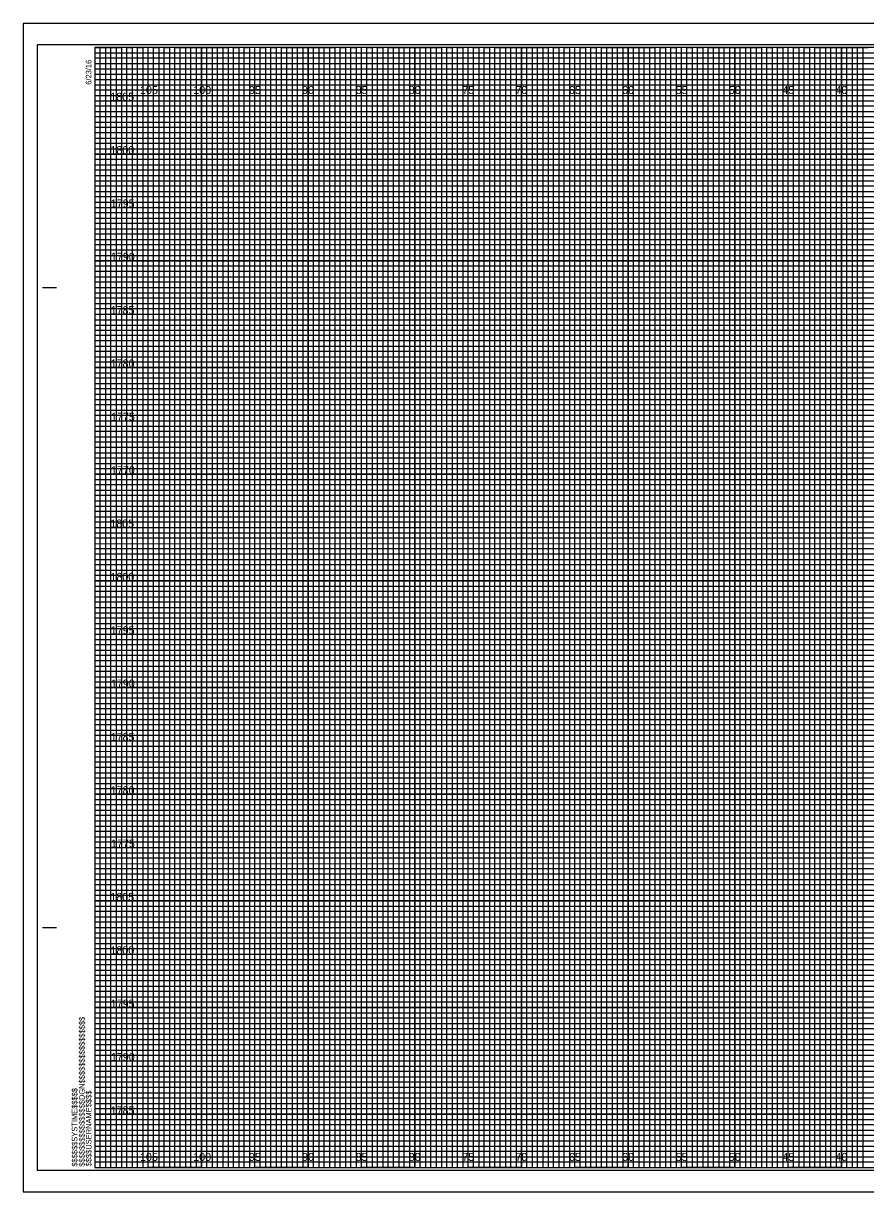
# Model space of a CAD drawing. Extents: x -7 to 392, y -2 to 440.
# Drawn here: x 223.6 to 302.5, y 1 to 110.5 of the extents above; entities that cross this region are included whole.
import ezdxf

# ---------------------------------------------------------------- set-up
doc = ezdxf.new("R2010")
doc.units = 0
for name, color, linetype in [('Prop Grid Mask', 7, 'Continuous'), ('Prop XS Elevation Labels', 7, 'Continuous'), ('Sheet Cross Section CELL', 7, 'Continuous'), ('Sheet Cross Section Grid Major CELL', 7, 'Continuous'), ('Sheet Cross Section Grid Middle CELL', 7, 'Continuous'), ('Sheet Cross Section Grid Minor 1 CELL', 7, 'Continuous'), ('Sheet Cross Section Grid Minor 2 CELL', 7, 'Continuous'), ('Sheet Cutting Line CELL', 7, 'Continuous'), ('Sheet DOT Grid CELL', 7, 'Continuous'), ('Sheet Plot Border Inside CELL', 7, 'Continuous'), ('Sheet Plot Border Outside CELL', 7, 'Continuous')]:
    doc.layers.add(name, color=color, linetype=linetype)

msp = doc.modelspace()

# ---------------------------------------------------------------- linework, layer by layer
at = {"layer": 'Sheet Cross Section CELL'}
for p, q in [((225.36, 85.71), (226.61, 85.71)), ((225.41, 85.71), (226.66, 85.71)), ((225.36, 25.71), (226.61, 25.71)), ((225.41, 25.71), (226.66, 25.71)), ((230.26, 3.21), (230.26, 3.21)), ((230.26, 3.21), (230.26, 3.21)), ((230.26, 3.21), (230.26, 3.21)), ((230.26, 3.21), (230.26, 3.21)), ((230.26, 3.21), (230.26, 3.21)), ((230.26, 3.21), (230.26, 3.21)), ((230.26, 3.21), (230.26, 3.21))]:
    msp.add_line(p, q, dxfattribs=at)
msp.add_lwpolyline([(390.26, 108.21), (230.26, 108.21), (230.26, 3.21), (390.26, 3.21)], close=True, dxfattribs=at)
at = {"layer": 'Sheet Cross Section Grid Major CELL'}
for p, q in [((235.26, 108.21), (230.26, 108.21)), ((235.26, 3.21), (235.26, 108.21)), ((245.26, 108.21), (240.26, 108.21)), ((240.26, 108.21), (240.26, 3.21)), ((245.26, 3.21), (245.26, 108.21)), ((255.26, 108.21), (250.26, 108.21)), ((250.26, 108.21), (250.26, 3.21)), ((255.26, 3.21), (255.26, 108.21)), ((265.26, 108.21), (260.26, 108.21)), ((260.26, 108.21), (260.26, 3.21)), ((265.26, 3.21), (265.26, 108.21)), ((275.26, 108.21), (270.26, 108.21)), ((270.26, 108.21), (270.26, 3.21)), ((275.26, 3.21), (275.26, 108.21)), ((285.26, 108.21), (280.26, 108.21)), ((280.26, 108.21), (280.26, 3.21)), ((285.26, 3.21), (285.26, 108.21)), ((295.26, 108.21), (290.26, 108.21)), ((290.26, 108.21), (290.26, 3.21)), ((295.26, 3.21), (295.26, 108.21)), ((305.26, 108.21), (300.26, 108.21)), ((300.26, 108.21), (300.26, 3.21)), ((240.26, 3.21), (235.26, 3.21)), ((250.26, 3.21), (245.26, 3.21)), ((260.26, 3.21), (255.26, 3.21)), ((270.26, 3.21), (265.26, 3.21)), ((280.26, 3.21), (275.26, 3.21)), ((290.26, 3.21), (285.26, 3.21)), ((300.26, 3.21), (295.26, 3.21))]:
    msp.add_line(p, q, dxfattribs=at)
for points in [[(230.26, 103.21), (390.26, 103.21), (390.26, 98.21), (230.26, 98.21)], [(230.26, 93.21), (390.26, 93.21), (390.26, 88.21), (230.26, 88.21)], [(230.26, 83.21), (390.26, 83.21), (390.26, 78.21), (230.26, 78.21)], [(230.26, 73.21), (390.26, 73.21), (390.26, 68.21), (230.26, 68.21)], [(230.26, 63.21), (390.26, 63.21), (390.26, 58.21), (230.26, 58.21)], [(230.26, 53.21), (390.26, 53.21), (390.26, 48.21), (230.26, 48.21)], [(230.26, 43.21), (390.26, 43.21), (390.26, 38.21), (230.26, 38.21)], [(230.26, 33.21), (390.26, 33.21), (390.26, 28.21), (230.26, 28.21)], [(230.26, 23.21), (390.26, 23.21), (390.26, 18.21), (230.26, 18.21)], [(230.26, 13.21), (390.26, 13.21), (390.26, 8.21), (230.26, 8.21)]]:
    msp.add_lwpolyline(points, dxfattribs=at)
at = {"layer": 'Sheet Cross Section Grid Middle CELL'}
for points in [[(230.26, 108.21), (232.76, 108.21), (232.76, 3.21), (237.76, 3.21), (237.76, 108.21), (242.76, 108.21), (242.76, 3.21), (247.76, 3.21), (247.76, 108.21), (252.76, 108.21), (252.76, 3.21), (257.76, 3.21), (257.76, 108.21), (262.76, 108.21), (262.76, 3.21), (267.76, 3.21), (267.76, 108.21), (272.76, 108.21), (272.76, 3.21), (277.76, 3.21), (277.76, 108.21), (282.76, 108.21), (282.76, 3.21), (287.76, 3.21), (287.76, 108.21), (292.76, 108.21), (292.76, 3.21), (297.76, 3.21), (297.76, 108.21), (302.76, 108.21)], [(230.26, 105.71), (367.76, 105.71)], [(230.26, 95.71), (390.26, 95.71), (390.26, 100.71), (230.26, 100.71)], [(230.26, 85.71), (390.26, 85.71), (390.26, 90.71), (230.26, 90.71)], [(230.26, 75.71), (390.26, 75.71), (390.26, 80.71), (230.26, 80.71)], [(230.26, 65.71), (390.26, 65.71), (390.26, 70.71), (230.26, 70.71)], [(230.26, 55.71), (390.26, 55.71), (390.26, 60.71), (230.26, 60.71)], [(230.26, 45.71), (390.26, 45.71), (390.26, 50.71), (230.26, 50.71)], [(230.26, 35.71), (390.26, 35.71), (390.26, 40.71), (230.26, 40.71)], [(230.26, 25.71), (390.26, 25.71), (390.26, 30.71), (230.26, 30.71)], [(230.26, 15.71), (390.26, 15.71), (390.26, 20.71), (230.26, 20.71)], [(230.26, 5.71), (390.26, 5.71), (390.26, 10.71), (230.26, 10.71)]]:
    msp.add_lwpolyline(points, dxfattribs=at)
at = {"layer": 'Sheet Cross Section Grid Minor 1 CELL'}
for p, q in [((230.26, 107.71), (360.26, 107.71)), ((360.26, 107.2), (230.26, 107.2)), ((230.26, 107.2), (230.26, 106.71)), ((230.26, 106.71), (360.26, 106.71)), ((360.26, 106.16), (230.26, 106.16)), ((230.26, 106.16), (230.26, 105.21)), ((230.26, 105.21), (390.26, 105.21))]:
    msp.add_line(p, q, dxfattribs=at)
for points in [[(230.26, 104.71), (365.26, 104.71), (390.26, 104.71), (390.26, 104.21), (230.26, 104.21)], [(230.26, 103.71), (390.26, 103.71), (390.26, 102.71), (230.26, 102.71)], [(230.26, 102.21), (390.26, 102.21), (390.26, 101.71), (230.26, 101.7)], [(230.26, 101.21), (390.26, 101.21), (390.26, 100.21), (230.26, 100.21)], [(230.26, 99.71), (390.26, 99.71), (390.26, 99.21), (230.26, 99.21)], [(230.26, 98.71), (390.26, 98.71), (390.26, 97.71), (230.26, 97.71)], [(230.26, 97.21), (390.26, 97.21), (390.26, 96.71), (230.26, 96.71)], [(230.26, 96.21), (390.26, 96.21), (390.26, 95.21), (230.26, 95.21)], [(230.26, 94.71), (390.26, 94.71), (390.26, 94.21), (230.26, 94.21)], [(230.26, 93.71), (390.26, 93.71), (390.26, 92.71), (230.26, 92.71)], [(230.26, 92.21), (390.26, 92.21), (390.26, 91.71), (230.26, 91.71)], [(230.26, 91.21), (390.26, 91.21), (390.26, 90.19), (390.26, 89.71), (390.26, 89.21), (230.26, 89.21)], [(230.26, 90.21), (390.26, 90.21), (390.26, 89.71), (230.26, 89.71)], [(230.26, 88.71), (390.26, 88.71), (390.26, 87.71), (230.26, 87.73)], [(230.26, 87.73), (390.26, 87.71), (390.26, 87.21), (230.26, 87.21)], [(230.26, 86.71), (390.26, 86.71), (390.26, 86.21), (230.26, 86.21)], [(230.26, 85.21), (390.26, 85.21), (390.26, 84.71), (230.26, 84.71)], [(230.26, 84.21), (390.26, 84.21), (390.26, 83.71), (230.26, 83.71)], [(230.23, 82.66), (390.26, 82.66), (390.26, 82.15), (230.23, 82.15)], [(230.26, 81.71), (390.26, 81.71), (390.26, 81.21), (230.26, 81.21)], [(230.26, 80.21), (390.26, 80.21), (390.26, 79.71), (230.26, 79.71)], [(230.26, 79.21), (390.26, 79.21), (390.26, 78.71), (230.26, 78.71)], [(230.26, 77.71), (390.26, 77.71), (390.26, 77.21), (230.26, 77.21)], [(230.26, 76.71), (390.26, 76.71), (390.26, 76.21), (230.26, 76.21)], [(230.26, 75.21), (390.26, 75.21), (390.26, 74.71), (230.26, 74.71)], [(230.26, 74.21), (390.26, 74.21), (390.26, 73.71), (230.26, 73.71)], [(230.26, 72.71), (390.26, 72.71), (390.26, 72.2), (230.26, 72.21)], [(230.26, 71.71), (390.26, 71.71), (390.26, 71.21), (230.26, 71.21)], [(230.26, 70.21), (390.26, 70.21), (390.26, 69.71), (230.26, 69.71)], [(230.26, 69.21), (390.26, 69.21), (390.26, 68.71), (230.26, 68.71)], [(230.26, 67.71), (390.26, 67.71), (390.26, 67.21), (230.26, 67.21)], [(230.26, 66.71), (390.26, 66.71), (390.26, 66.21), (230.26, 66.21)], [(230.26, 65.21), (390.26, 65.21), (390.26, 64.71), (230.26, 64.71)], [(230.26, 64.21), (390.26, 64.21), (390.26, 63.71), (230.26, 63.71)], [(230.26, 62.71), (390.26, 62.71), (390.26, 62.21), (230.26, 62.21)], [(230.26, 61.71), (390.3, 61.67), (390.26, 61.21), (230.26, 61.21)], [(230.26, 60.21), (390.26, 60.21), (390.26, 59.71), (230.26, 59.71)], [(230.26, 59.21), (390.26, 59.21), (390.26, 58.71), (230.26, 58.71)], [(230.26, 57.71), (390.26, 57.71), (390.26, 57.21), (230.26, 57.21)], [(230.26, 56.71), (390.26, 56.71), (390.26, 56.21), (230.26, 56.21)], [(230.26, 55.21), (390.26, 55.21), (390.26, 54.71), (230.26, 54.71)], [(230.26, 54.21), (390.26, 54.21), (390.26, 53.71), (230.26, 53.71)], [(230.26, 52.71), (390.26, 52.71), (390.26, 52.21), (230.26, 52.21)], [(230.26, 51.71), (390.26, 51.71), (390.26, 51.21), (230.26, 51.21)], [(230.26, 50.21), (390.26, 50.21), (390.26, 49.71), (230.26, 49.71)], [(230.26, 49.21), (390.26, 49.21), (390.26, 48.71), (230.26, 48.71)], [(230.26, 47.71), (390.26, 47.71), (390.26, 47.21), (230.26, 47.21)], [(230.26, 46.71), (390.26, 46.71), (390.26, 46.21), (230.26, 46.21)], [(230.26, 45.21), (390.26, 45.21), (390.26, 44.71), (230.26, 44.71)], [(230.26, 44.21), (390.26, 44.21), (390.26, 43.71), (230.26, 43.71)], [(230.26, 42.71), (390.26, 42.71), (390.26, 42.2), (230.26, 42.21)], [(230.26, 41.71), (390.26, 41.71), (390.26, 41.21), (230.26, 41.21)], [(230.26, 40.21), (390.26, 40.21), (390.26, 39.71), (230.26, 39.71)], [(230.26, 39.21), (390.26, 39.21), (390.26, 38.71), (230.26, 38.71)], [(230.26, 37.71), (390.26, 37.71), (390.26, 37.21), (230.26, 37.21)], [(230.26, 36.71), (390.26, 36.71), (390.26, 36.21), (230.26, 36.21)], [(230.26, 35.21), (390.26, 35.21), (390.26, 34.71), (230.26, 34.71)], [(230.26, 34.21), (390.26, 34.21), (390.26, 33.71), (230.26, 33.71)], [(230.26, 32.71), (390.26, 32.71), (390.26, 32.21), (230.26, 32.21)], [(230.26, 31.71), (390.3, 31.67), (390.26, 31.21), (230.26, 31.21)], [(230.26, 30.21), (390.26, 30.21), (390.26, 29.71), (230.26, 29.71)], [(230.26, 29.21), (390.26, 29.21), (390.26, 28.71), (230.26, 28.71)], [(230.26, 27.71), (390.26, 27.71), (390.26, 27.21), (230.26, 27.21)], [(230.26, 26.71), (390.26, 26.71), (390.26, 26.21), (230.26, 26.21)], [(230.26, 25.21), (390.26, 25.21), (390.26, 24.71), (230.26, 24.71)], [(230.26, 24.21), (390.26, 24.21), (390.26, 23.71), (230.26, 23.71)], [(230.26, 22.71), (390.26, 22.71), (390.26, 22.21), (230.26, 22.21)], [(230.26, 21.71), (390.26, 21.71), (390.26, 21.21), (230.26, 21.21)], [(230.26, 20.21), (390.26, 20.21), (390.26, 19.71), (230.26, 19.71)], [(230.26, 19.21), (390.26, 19.21), (390.26, 18.71), (230.26, 18.71)], [(230.26, 17.71), (390.26, 17.71), (390.26, 17.21), (230.26, 17.21)], [(230.26, 16.71), (390.26, 16.71), (390.26, 16.21), (230.26, 16.21)], [(230.26, 15.21), (390.26, 15.21), (390.26, 14.71), (230.26, 14.71)], [(230.26, 14.21), (390.26, 14.21), (390.26, 13.71), (230.26, 13.71)], [(230.26, 12.71), (390.26, 12.71), (390.26, 12.21), (230.26, 12.21)], [(230.26, 11.71), (390.26, 11.71), (390.26, 11.21), (230.26, 11.21)], [(230.26, 10.21), (390.26, 10.21), (390.26, 9.71), (230.26, 9.71)], [(230.26, 9.21), (390.26, 9.21), (390.26, 8.71), (230.26, 8.71)], [(230.26, 7.71), (390.26, 7.71), (390.26, 7.21), (230.26, 7.21)], [(230.26, 6.71), (390.26, 6.71), (390.26, 6.21), (230.26, 6.21)], [(230.26, 5.21), (390.26, 5.21), (390.26, 4.71), (230.26, 4.71)], [(230.26, 4.21), (390.26, 4.21), (390.26, 3.71), (230.26, 3.71)]]:
    msp.add_lwpolyline(points, dxfattribs=at)
at = {"layer": 'Sheet Cross Section Grid Minor 2 CELL'}
for points in [[(230.26, 3.21), (230.76, 3.21), (230.76, 108.21), (231.26, 108.21), (231.26, 3.21)], [(231.26, 3.21), (231.76, 3.21), (231.76, 108.21), (232.26, 108.21), (232.26, 3.21)], [(232.76, 3.21), (233.26, 3.21), (233.26, 108.21), (233.76, 108.21), (233.76, 3.21)], [(233.76, 3.21), (234.26, 3.21), (234.26, 108.21), (234.76, 108.21), (234.76, 3.21)], [(235.26, 3.21), (235.76, 3.21), (235.76, 108.21), (236.26, 108.21), (236.26, 3.21)], [(236.26, 3.21), (236.76, 3.21), (236.76, 108.21), (237.26, 108.21), (237.26, 3.21)], [(237.76, 3.21), (238.26, 3.21), (238.26, 108.21), (238.76, 108.21), (238.76, 3.21)], [(238.76, 3.21), (239.26, 3.21), (239.26, 108.21), (239.76, 108.21), (239.76, 3.21)], [(240.26, 3.21), (240.76, 3.21), (240.76, 108.21), (241.26, 108.21), (241.26, 3.21)], [(241.26, 3.21), (241.76, 3.21), (241.76, 108.21), (242.26, 108.21), (242.26, 3.21)], [(242.76, 3.21), (243.26, 3.21), (243.26, 108.21), (243.76, 108.21), (243.76, 3.21)], [(243.76, 3.21), (244.26, 3.21), (244.26, 108.21), (244.76, 108.21), (244.76, 3.21)], [(245.26, 3.21), (245.76, 3.21), (245.76, 108.21), (246.26, 108.21), (246.26, 3.21)], [(246.26, 3.21), (246.76, 3.21), (246.76, 108.21), (247.26, 108.21), (247.26, 3.21)], [(247.76, 3.21), (248.26, 3.21), (248.26, 108.21), (248.76, 108.21), (248.76, 3.21)], [(248.76, 3.21), (249.26, 3.21), (249.26, 108.21), (249.76, 108.21), (249.76, 3.21)], [(250.26, 3.21), (250.76, 3.21), (250.76, 108.21), (251.26, 108.21), (251.26, 3.21)], [(251.26, 3.21), (251.76, 3.21), (251.76, 108.21), (252.26, 108.21), (252.26, 3.21)], [(252.76, 3.21), (253.26, 3.21), (253.26, 108.21), (253.76, 108.21), (253.76, 3.21)], [(253.76, 3.21), (254.26, 3.21), (254.26, 108.21), (254.76, 108.21), (254.76, 3.21)], [(255.26, 3.21), (255.76, 3.21), (255.76, 108.21), (256.26, 108.21), (256.26, 3.21)], [(256.26, 3.21), (256.76, 3.21), (256.76, 108.21), (257.26, 108.21), (257.26, 3.21)], [(257.76, 3.21), (258.26, 3.21), (258.26, 108.21), (258.76, 108.21), (258.76, 3.21)], [(258.76, 3.21), (259.26, 3.21), (259.26, 108.21), (259.76, 108.21), (259.76, 3.21)], [(260.26, 3.21), (260.76, 3.21), (260.76, 108.21), (261.26, 108.21), (261.26, 3.21)], [(261.26, 3.21), (261.76, 3.21), (261.76, 108.21), (262.26, 108.21), (262.26, 3.21)], [(262.76, 3.21), (263.26, 3.21), (263.26, 108.21), (263.76, 108.21), (263.76, 3.21)], [(263.76, 3.21), (264.26, 3.21), (264.26, 108.21), (264.76, 108.21), (264.76, 3.21)], [(265.26, 3.21), (265.76, 3.21), (265.76, 108.21), (266.26, 108.21), (266.26, 3.21)], [(266.26, 3.21), (266.76, 3.21), (266.76, 108.21), (267.26, 108.21), (267.26, 3.21)], [(267.76, 3.21), (268.26, 3.21), (268.26, 108.21), (268.76, 108.21), (268.76, 3.21)], [(268.76, 3.21), (269.26, 3.21), (269.26, 108.21), (269.76, 108.21), (269.76, 3.21)], [(270.26, 3.21), (270.76, 3.21), (270.76, 108.21), (271.26, 108.21), (271.26, 3.21)], [(271.26, 3.21), (271.76, 3.21), (271.76, 108.21), (272.26, 108.21), (272.26, 3.21)], [(272.76, 3.21), (273.26, 3.21), (273.26, 108.21), (273.76, 108.21), (273.76, 3.21)], [(273.76, 3.21), (274.26, 3.21), (274.26, 108.21), (274.76, 108.21), (274.76, 3.21)], [(275.26, 3.21), (275.76, 3.21), (275.76, 108.21), (276.26, 108.21), (276.26, 3.21)], [(276.26, 3.21), (276.76, 3.21), (276.76, 108.21), (277.26, 108.21), (277.26, 3.21)], [(277.76, 3.21), (278.26, 3.21), (278.26, 108.21), (278.76, 108.21), (278.76, 3.21)], [(278.76, 3.21), (279.26, 3.21), (279.26, 108.21), (279.76, 108.21), (279.76, 3.21)], [(280.26, 3.21), (280.76, 3.21), (280.76, 108.21), (281.26, 108.21), (281.26, 3.21)], [(281.26, 3.21), (281.76, 3.21), (281.76, 108.21), (282.26, 108.21), (282.26, 3.21)], [(282.76, 3.21), (283.26, 3.21), (283.26, 108.21), (283.76, 108.21), (283.76, 3.21)], [(283.76, 3.21), (284.26, 3.21), (284.26, 108.21), (284.76, 108.21), (284.76, 3.21)], [(285.26, 3.21), (285.76, 3.21), (285.76, 108.21), (286.26, 108.21), (286.26, 3.21)], [(286.26, 3.21), (286.76, 3.21), (286.76, 108.21), (287.26, 108.21), (287.26, 3.21)], [(287.76, 3.21), (288.26, 3.21), (288.26, 108.21), (288.76, 108.21), (288.76, 3.21)], [(288.76, 3.21), (289.26, 3.21), (289.26, 108.21), (289.76, 108.21), (289.76, 3.21)], [(290.26, 3.21), (290.76, 3.21), (290.76, 108.21), (291.26, 108.21), (291.26, 3.21)], [(291.26, 3.21), (291.76, 3.21), (291.76, 108.21), (292.26, 108.21), (292.26, 3.21)], [(292.76, 3.21), (293.26, 3.21), (293.26, 108.21), (293.76, 108.21), (293.76, 3.21)], [(293.76, 3.21), (294.26, 3.21), (294.26, 108.21), (294.76, 108.21), (294.76, 3.21)], [(295.26, 3.21), (295.76, 3.21), (295.76, 108.21), (296.26, 108.21), (296.26, 3.21)], [(296.26, 3.21), (296.76, 3.21), (296.76, 108.21), (297.26, 108.21), (297.26, 3.21)], [(297.76, 3.21), (298.26, 3.21), (298.26, 108.21), (298.76, 108.21), (298.76, 3.21)], [(298.76, 3.21), (299.26, 3.21), (299.26, 108.21), (299.76, 108.21), (299.76, 3.21)], [(300.26, 3.21), (300.76, 3.21), (300.76, 108.21), (301.26, 108.21), (301.26, 3.21)], [(301.26, 3.21), (301.76, 3.21), (301.76, 108.21), (302.26, 108.21), (302.26, 3.21)]]:
    msp.add_lwpolyline(points, dxfattribs=at)
at = {"layer": 'Sheet Cutting Line CELL'}
for p, q in [((391.91, 110.46), (223.56, 110.46)), ((223.56, 110.46), (223.56, 0.96)), ((223.56, 0.96), (391.91, 0.96))]:
    msp.add_line(p, q, dxfattribs=at)
at = {"layer": 'Sheet DOT Grid CELL'}
for p, q in [((235.26, 3.21), (235.26, 108.21)), ((240.26, 3.21), (240.26, 108.21)), ((245.26, 3.21), (245.26, 108.21)), ((250.26, 3.21), (250.26, 108.21)), ((255.26, 3.21), (255.26, 108.21)), ((260.26, 3.21), (260.26, 108.21)), ((265.26, 3.21), (265.26, 108.21)), ((270.26, 3.21), (270.26, 108.21)), ((275.26, 3.21), (275.26, 108.21)), ((280.26, 3.21), (280.26, 108.21)), ((285.26, 3.21), (285.26, 108.21)), ((290.26, 3.21), (290.26, 108.21)), ((295.26, 3.21), (295.26, 108.21)), ((300.26, 3.21), (300.26, 108.21)), ((230.26, 103.21), (390.26, 103.21)), ((230.26, 98.21), (390.26, 98.21)), ((230.26, 93.21), (390.26, 93.21)), ((230.26, 88.21), (390.26, 88.21)), ((230.26, 83.21), (390.26, 83.21)), ((230.26, 78.21), (390.26, 78.21)), ((230.26, 73.21), (390.26, 73.21)), ((230.26, 68.21), (390.26, 68.21)), ((230.26, 63.21), (390.26, 63.21)), ((230.26, 58.21), (390.26, 58.21)), ((230.26, 53.21), (390.26, 53.21)), ((230.26, 48.21), (390.26, 48.21)), ((230.26, 43.21), (390.26, 43.21)), ((230.26, 38.21), (390.26, 38.21)), ((230.26, 33.21), (390.26, 33.21)), ((230.26, 28.21), (390.26, 28.21)), ((230.26, 23.21), (390.26, 23.21)), ((230.26, 18.21), (390.26, 18.21)), ((230.26, 13.21), (390.26, 13.21)), ((230.26, 8.21), (390.26, 8.21))]:
    msp.add_line(p, q, dxfattribs=at)
at = {"layer": 'Sheet Plot Border Inside CELL'}
msp.add_lwpolyline([(224.86, 2.96), (391.46, 2.96), (391.46, 108.46), (224.86, 108.46)], close=True, dxfattribs=at)
at = {"layer": 'Sheet Plot Border Outside CELL'}
msp.add_lwpolyline([(223.56, 0.96), (391.91, 0.96), (391.91, 110.46), (223.56, 110.46)], close=True, dxfattribs=at)

# ---------------------------------------------------------------- texts
at = {"layer": 'Prop Grid Mask'}
for s, p in [('105', (234.5, 103.84)), ('100', (239.49, 103.84)), ('95', (244.71, 103.84)), ('90', (249.69, 103.84)), ('85', (254.71, 103.84)), ('80', (259.69, 103.84)), ('75', (264.71, 103.84)), ('70', (269.69, 103.84)), ('65', (274.71, 103.84)), ('60', (279.69, 103.84)), ('55', (284.71, 103.84)), ('50', (289.69, 103.84)), ('45', (294.71, 103.84)), ('40', (299.69, 103.84)), ('105', (234.5, 3.84)), ('100', (239.49, 3.84)), ('95', (244.71, 3.84)), ('90', (249.69, 3.84)), ('85', (254.71, 3.84)), ('80', (259.69, 3.84)), ('75', (264.71, 3.84)), ('70', (269.69, 3.84)), ('65', (274.71, 3.84)), ('60', (279.69, 3.84)), ('55', (284.71, 3.84)), ('50', (289.69, 3.84)), ('45', (294.71, 3.84)), ('40', (299.69, 3.84))]:
    msp.add_text(s, height=0.75, dxfattribs=at).set_placement(p)
at = {"layer": 'Prop XS Elevation Labels'}
for s, p in [('1805', (231.72, 103.21)), ('1800', (231.73, 98.21)), ('1795', (231.76, 93.21)), ('1790', (231.77, 88.21)), ('1785', (231.75, 83.21)), ('1780', (231.75, 78.21)), ('1775', (231.78, 73.21)), ('1770', (231.78, 68.21)), ('1805', (231.72, 63.21)), ('1800', (231.73, 58.21)), ('1795', (231.76, 53.21)), ('1790', (231.77, 48.21)), ('1785', (231.75, 43.21)), ('1780', (231.75, 38.21)), ('1775', (231.78, 33.21)), ('1805', (231.72, 28.21)), ('1800', (231.73, 23.21)), ('1795', (231.76, 18.21)), ('1790', (231.77, 13.21)), ('1785', (231.75, 8.21))]:
    msp.add_text(s, height=0.75, dxfattribs=at).set_placement(p)
at = {"layer": 'Sheet Cross Section CELL'}
for s, p in [('6/23/16', (229.94, 104.71)), ('$$$$$$$$$$$$$$$$DGN$$$$$$$$$$$$$$$$', (229.32, 3.3)), ('$$$$$$SYSTIME$$$$$', (228.63, 3.3)), ('$$$$USERNAME$$$$', (229.95, 3.33))]:
    msp.add_text(s, height=0.525, rotation=90, dxfattribs=at).set_placement(p)

doc.saveas('drawing.dxf')
